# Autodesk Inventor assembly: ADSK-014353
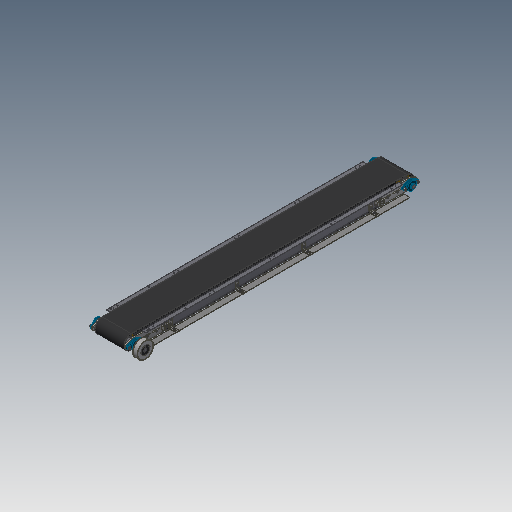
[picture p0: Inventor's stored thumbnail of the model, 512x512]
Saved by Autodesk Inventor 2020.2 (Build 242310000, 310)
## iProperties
Created: 2019-10
Part Number: ADSK-014353
Document SubType Name: Assembly
Designer: lutzd
Mass: 90371.3 g
Surface Area: 57832.2 cm^2
Volume: 15767.9 cm^3
Density: 5.73136 g/cm^3
VLDS_Profile: Default Assembly
VLDS_TimeStamp: 2016-07-29
VLDS_FailCnt: 0
VLDS_AcceptCnt: 0
Dimensions: 2353,4x1828,9x416 mm
Mass: 90,371 kg
DocNumber: ADSK-014353
Folder: 01 - Themengebiete\Simplification\01 - Packaging machine\
VDS_Category: 3D Komponenten
VDS_NumSchm: Autodesk
Title: belt conveyor
Author: lutzd
Revision Number: -
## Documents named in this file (23)
- D:\07 - DEMODATEN\OTX 2019 - Dataset - UPDATE - Dez2019\Designs\07-Packing machine\ADSK-014353.iam
- D:\07 - DEMODATEN\OTX 2019 - Dataset - UPDATE - Dez2019\Designs\07-Packing machine\500533.iam
- D:\07 - DEMODATEN\OTX 2019 - Dataset - UPDATE - Dez2019\Designs\07-Packing machine\Parts\ADSK-011789.ipt
- D:\07 - DEMODATEN\OTX 2019 - Dataset - UPDATE - Dez2019\Designs\07-Packing machine\Parts\ADSK-011476.ipt
- D:\07 - DEMODATEN\OTX 2019 - Dataset - UPDATE - Dez2019\Designs\07-Packing machine\Parts\ADSK-011712.ipt
- D:\07 - DEMODATEN\OTX 2019 - Dataset - UPDATE - Dez2019\Designs\07-Packing machine\Parts\ADSK-011477.ipt
- D:\07 - DEMODATEN\OTX 2019 - Dataset - UPDATE - Dez2019\Designs\07-Packing machine\Parts\ADSK-014338.ipt
- D:\07 - DEMODATEN\OTX 2019 - Dataset - UPDATE - Dez2019\Content Center Files\de-DE\DIN 125-1  B\DIN 125-1 - B 6,4.ipt
- D:\07 - DEMODATEN\OTX 2019 - Dataset - UPDATE - Dez2019\Content Center Files\de-DE\ISO 4032(1)\ISO 4032 - M6DIN EN.ipt
- D:\07 - DEMODATEN\OTX 2019 - Dataset - UPDATE - Dez2019\Content Center Files\de-DE\ISO 4762(2)\ISO 4762 - M6 x 20ISO.ipt
- D:\07 - DEMODATEN\OTX 2019 - Dataset - UPDATE - Dez2019\Content Center Files\de-DE\DIN 125-1  B\DIN 125-1 - B 8,4.ipt
- D:\07 - DEMODATEN\OTX 2019 - Dataset - UPDATE - Dez2019\Content Center Files\de-DE\ISO 4032(1)\ISO 4032 - M8DIN EN.ipt
- D:\07 - DEMODATEN\OTX 2019 - Dataset - UPDATE - Dez2019\Content Center Files\de-DE\ISO 4762(2)\ISO 4762 - M8 x 25ISO.ipt
- D:\07 - DEMODATEN\OTX 2019 - Dataset - UPDATE - Dez2019\Content Center Files\de-DE\ISO 4762(2)\ISO 4762 - M8 x 45ISO.ipt
- D:\07 - DEMODATEN\OTX 2019 - Dataset - UPDATE - Dez2019\Content Center Files\de-DE\DIN 125-1  B\DIN 125-1 - B 10,5.ipt
- D:\07 - DEMODATEN\OTX 2019 - Dataset - UPDATE - Dez2019\Content Center Files\de-DE\ISO 4762(2)\ISO 4762 - M10 x 25ISO.ipt
- D:\07 - DEMODATEN\OTX 2019 - Dataset - UPDATE - Dez2019\Content Center Files\de-DE\DIN 471(2)\DIN 471 - 52 x 2(1).ipt
- D:\07 - DEMODATEN\OTX 2019 - Dataset - UPDATE - Dez2019\Content Center Files\de-DE\ISO 2491 - A\ISO 2491 - A  6 x 4 x 36.ipt
- D:\07 - DEMODATEN\OTX 2019 - Dataset - UPDATE - Dez2019\Designs\07-Packing machine\ADSK-014342.iam
- D:\07 - DEMODATEN\OTX 2019 - Dataset - UPDATE - Dez2019\Designs\07-Packing machine\Parts\ADSK-014357.ipt
- D:\07 - DEMODATEN\OTX 2019 - Dataset - UPDATE - Dez2019\Designs\07-Packing machine\ADSK-014358.iam
- D:\07 - DEMODATEN\OTX 2019 - Dataset - UPDATE - Dez2019\Designs\07-Packing machine\Parts\ADSK-014367.ipt
- D:\07 - DEMODATEN\OTX 2019 - Dataset - UPDATE - Dez2019\Designs\07-Packing machine\Parts\ADSK-014506.ipt
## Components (188 placed, 22 different names)
1. ADSK-014358:1 [sub-assembly] — Passend:165, Passend:166, Passend:167, Passend:168, Fluchtend:10, Fluchtend:11, Fluchtend:12, Fluchtend:13, Passend:169, Passend:170, Passend:171, Passend:172, Passend:173, Passend:174, Passend:177, Passend:178, Passend:181, Passend:182, Passend:185, Passend:186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
2. 500533:1 [sub-assembly]
3. ADSK-011789:1
4. ADSK-011476:1
5. ADSK-011712:1
6. 500533:2 [sub-assembly]
7. ADSK-011712:2
8. 500533:3 [sub-assembly]
9. 500533:4 [sub-assembly]
10. ADSK-011477:1
11. ADSK-011712:3
12. ADSK-011712:4
13. ADSK-011789:2
14. ADSK-011789:3
15. ADSK-011789:4
16. ADSK-014357:1
17. ADSK-014338:1 — Passend:195, Passend:197, Passend:199, Passend:224, Passend:226, Passend:228, Passend:230
18. ADSK-014338:2
19. ADSK-014338:3
20. ADSK-014338:4 — Passend:201, Passend:203, Passend:205, Passend:207
21. ADSK-014342:1 [sub-assembly]
22. ADSK-014338:5 — Passend:165, Fluchtend:13, Passend:169, Passend:187, Passend:188
23. ADSK-014338:6 — Passend:166, Fluchtend:12, Passend:170, Passend:183, Passend:184, Passend:189, Fluchtend:15
24. ADSK-014338:7 — Passend:167, Fluchtend:11, Passend:171, Passend:175, Passend:176
25. ADSK-014338:8 — Passend:168, Fluchtend:10, Passend:172, Passend:179, Passend:180, Passend:191, Fluchtend:16
26. ADSK-014506:1 — Fluchtend:14, Passend:189, Fluchtend:15
27. ADSK-014367:2 — Passend:190, Passend:191, Fluchtend:16
28. DIN 125-1 B B 6,4:49
29. DIN 125-1 B B 6,4:50 — Passend:226
30. DIN 125-1 B B 6,4:51 — Passend:228
31. DIN 125-1 B B 6,4:52 — Passend:230
32. DIN 125-1 B B 6,4:53
33. DIN 125-1 B B 6,4:54
34. DIN EN 24032 M6:24
35. DIN EN 24032 M6:25
36. ISO 4762 M6 x 20:25
37. ISO 4762 M6 x 20:26
38. DIN EN 24032 M6:26
39. ISO 4762 M6 x 20:27
40. DIN 125-1 B B 6,4:34
41. DIN 125-1 B B 6,4:35
42. DIN 125-1 B B 6,4:36
43. DIN 125-1 B B 6,4:38 — Passend:195
44. DIN 125-1 B B 6,4:39 — Passend:197
45. DIN 125-1 B B 6,4:40 — Passend:199
46. DIN 125-1 B B 6,4:41 — Passend:217, Passend:219, Passend:221, Passend:223
47. DIN 125-1 B B 6,4:42
48. DIN 125-1 B B 6,4:43
49. DIN 125-1 B B 6,4:44
50. DIN 125-1 B B 6,4:45 — Passend:201
51. DIN 125-1 B B 6,4:46 — Passend:203
52. DIN 125-1 B B 6,4:47 — Passend:205
53. DIN 125-1 B B 6,4:48 — Passend:207
54. DIN EN 24032 M6:17
55. DIN EN 24032 M6:18
56. DIN EN 24032 M6:19
57. DIN EN 24032 M6:20
58. DIN EN 24032 M6:21
59. DIN EN 24032 M6:22
60. DIN EN 24032 M6:23
61. ISO 4762 M6 x 20:18
62. ISO 4762 M6 x 20:19
63. ISO 4762 M6 x 20:20
64. ISO 4762 M6 x 20:21 — Passend:217
65. ISO 4762 M6 x 20:22 — Passend:219
66. ISO 4762 M6 x 20:23 — Passend:221
67. ISO 4762 M6 x 20:24 — Passend:223
68. DIN 125-1 B B 6,4:17 — Einfügen:42, Passend:175
69. ISO 4762 M6 x 20:9 — Einfügen:42, Passend:173
70. DIN 125-1 B B 6,4:18 — Passend:176
71. ISO 4762 M6 x 20:10 — Passend:174
72. DIN 125-1 B B 6,4:19 — Passend:179
73. ISO 4762 M6 x 20:11 — Passend:177
74. DIN 125-1 B B 6,4:20 — Passend:180
75. ISO 4762 M6 x 20:12 — Passend:178
76. DIN 125-1 B B 6,4:21 — Passend:183
77. ISO 4762 M6 x 20:13 — Passend:181
78. DIN 125-1 B B 6,4:22 — Passend:184
79. ISO 4762 M6 x 20:14 — Passend:182
80. DIN 125-1 B B 6,4:23 — Passend:188
81. ISO 4762 M6 x 20:15 — Passend:185
82. DIN 125-1 B B 6,4:24 — Passend:187
83. ISO 4762 M6 x 20:16 — Passend:186
84. DIN 125-1 B B 6,4:25 — Einfügen:56
85. DIN EN 24032 M6:9
86. DIN 125-1 B B 6,4:26 — Einfügen:57
87. DIN EN 24032 M6:10
88. DIN 125-1 B B 6,4:27 — Einfügen:55
89. DIN EN 24032 M6:11
90. DIN 125-1 B B 6,4:28 — Einfügen:54
91. DIN EN 24032 M6:12
92. DIN 125-1 B B 6,4:29 — Einfügen:62
93. DIN EN 24032 M6:13
94. DIN 125-1 B B 6,4:30 — Einfügen:63
95. DIN EN 24032 M6:14
96. DIN 125-1 B B 6,4:31 — Einfügen:64
97. DIN EN 24032 M6:15
98. DIN 125-1 B B 6,4:32 — Einfügen:65
99. DIN EN 24032 M6:16
100. DIN 125-1 B B 6,4:2
101. DIN 125-1 B B 6,4:4
102. DIN 125-1 B B 6,4:6
103. DIN 125-1 B B 6,4:8
104. DIN 125-1 B B 6,4:9
105. DIN 125-1 B B 6,4:10
106. DIN 125-1 B B 6,4:11
107. DIN 125-1 B B 6,4:12
108. DIN 125-1 B B 6,4:13
109. DIN 125-1 B B 6,4:14
110. DIN 125-1 B B 6,4:15
111. DIN 125-1 B B 6,4:16
112. DIN EN 24032 M6:1
113. DIN EN 24032 M6:2
114. DIN EN 24032 M6:3
115. DIN EN 24032 M6:4
116. DIN EN 24032 M6:7
117. DIN EN 24032 M6:8
118. ISO 4762 M6 x 20:1
119. ISO 4762 M6 x 20:4
120. ISO 4762 M6 x 20:5
121. ISO 4762 M6 x 20:6
122. ISO 4762 M6 x 20:7
123. ISO 4762 M6 x 20:8
124. DIN 125-1 B B 8,4:1
125. DIN 125-1 B B 8,4:2
126. DIN 125-1 B B 8,4:3
127. DIN 125-1 B B 8,4:4
128. DIN 125-1 B B 8,4:5
129. DIN 125-1 B B 8,4:6
130. DIN 125-1 B B 8,4:7
131. DIN 125-1 B B 8,4:8
132. DIN 125-1 B B 8,4:9
133. DIN 125-1 B B 8,4:10
134. DIN 125-1 B B 8,4:11
135. DIN 125-1 B B 8,4:12
136. DIN 125-1 B B 8,4:13
137. DIN 125-1 B B 8,4:14
138. DIN 125-1 B B 8,4:15
139. DIN 125-1 B B 8,4:16
140. DIN EN 24032 M8:1
141. DIN EN 24032 M8:2
142. DIN EN 24032 M8:3
143. DIN EN 24032 M8:4
144. DIN EN 24032 M8:5
145. DIN EN 24032 M8:6
146. DIN EN 24032 M8:7
147. DIN EN 24032 M8:8
148. ISO 4762 M8 x 25:1
149. ISO 4762 M8 x 25:2
150. ISO 4762 M8 x 25:3
151. ISO 4762 M8 x 25:4
152. ISO 4762 M8 x 25:5
153. ISO 4762 M8 x 25:6
154. ISO 4762 M8 x 25:7
155. ISO 4762 M8 x 25:8
156. ISO 4762 M8 x 45:1
157. ISO 4762 M8 x 45:2
158. ISO 4762 M8 x 45:3
159. ISO 4762 M8 x 45:4
160. DIN EN 24032 M8:9
161. DIN EN 24032 M8:10
162. DIN EN 24032 M8:11
163. DIN EN 24032 M8:12
164. DIN 125-1 B B 10,5:1
165. DIN 125-1 B B 10,5:2
166. DIN 125-1 B B 10,5:3
167. DIN 125-1 B B 10,5:4
168. DIN 125-1 B B 10,5:5
169. DIN 125-1 B B 10,5:6
170. DIN 125-1 B B 10,5:7
171. DIN 125-1 B B 10,5:8
172. ISO 4762 M10 x 25:1
173. ISO 4762 M10 x 25:2
174. ISO 4762 M10 x 25:3
175. ISO 4762 M10 x 25:4
176. ISO 4762 M10 x 25:5
177. ISO 4762 M10 x 25:6
178. ISO 4762 M10 x 25:7
179. ISO 4762 M10 x 25:8
180. DIN 471 > 9mm <= 300mm 52 x 2:1
181. DIN 471 > 9mm <= 300mm 52 x 2:2
182. DIN 471 > 9mm <= 300mm 52 x 2:3
183. DIN 471 > 9mm <= 300mm 52 x 2:4
184. DIN 471 > 9mm <= 300mm 52 x 2:5
185. DIN 471 > 9mm <= 300mm 52 x 2:6
186. DIN 471 > 9mm <= 300mm 52 x 2:7
187. DIN 471 > 9mm <= 300mm 52 x 2:8
188. ISO 2491 A A  6 x 4 x 36:1
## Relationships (58: Mate 42, Insert 9, Flush 7)
- Passend:165 [Mate]: ADSK-014358:1 ↔ ADSK-014338:5
- Passend:166 [Mate]: ADSK-014358:1 ↔ ADSK-014338:6
- Passend:167 [Mate]: ADSK-014358:1 ↔ ADSK-014338:7
- Passend:168 [Mate]: ADSK-014358:1 ↔ ADSK-014338:8
- Fluchtend:10 [Flush]: ADSK-014358:1 ↔ ADSK-014338:8
- Fluchtend:11 [Flush]: ADSK-014358:1 ↔ ADSK-014338:7
- Fluchtend:12 [Flush]: ADSK-014358:1 ↔ ADSK-014338:6
- Fluchtend:13 [Flush]: ADSK-014358:1 ↔ ADSK-014338:5
- Passend:169 [Mate]: ADSK-014358:1 ↔ ADSK-014338:5
- Passend:170 [Mate]: ADSK-014358:1 ↔ ADSK-014338:6
- Passend:171 [Mate]: ADSK-014358:1 ↔ ADSK-014338:7
- Passend:172 [Mate]: ADSK-014358:1 ↔ ADSK-014338:8
- Einfügen:42 [Insert]: DIN 125-1 B B 6,4:17 ↔ ISO 4762 M6 x 20:9
- Passend:173 [Mate]: ADSK-014358:1 ↔ ISO 4762 M6 x 20:9
- Passend:174 [Mate]: ADSK-014358:1 ↔ ISO 4762 M6 x 20:10
- Passend:175 [Mate]: ADSK-014338:7 ↔ DIN 125-1 B B 6,4:17
- Passend:176 [Mate]: ADSK-014338:7 ↔ DIN 125-1 B B 6,4:18
- Passend:177 [Mate]: ADSK-014358:1 ↔ ISO 4762 M6 x 20:11
- Passend:178 [Mate]: ADSK-014358:1 ↔ ISO 4762 M6 x 20:12
- Passend:179 [Mate]: ADSK-014338:8 ↔ DIN 125-1 B B 6,4:19
- Passend:180 [Mate]: ADSK-014338:8 ↔ DIN 125-1 B B 6,4:20
- Passend:181 [Mate]: ADSK-014358:1 ↔ ISO 4762 M6 x 20:13
- Passend:182 [Mate]: ADSK-014358:1 ↔ ISO 4762 M6 x 20:14
- Passend:183 [Mate]: ADSK-014338:6 ↔ DIN 125-1 B B 6,4:21
- Passend:184 [Mate]: ADSK-014338:6 ↔ DIN 125-1 B B 6,4:22
- Passend:185 [Mate]: ADSK-014358:1 ↔ ISO 4762 M6 x 20:15
- Passend:186 [Mate]: ADSK-014358:1 ↔ ISO 4762 M6 x 20:16
- Passend:187 [Mate]: ADSK-014338:5 ↔ DIN 125-1 B B 6,4:24
- Passend:188 [Mate]: ADSK-014338:5 ↔ DIN 125-1 B B 6,4:23
- Einfügen:54 [Insert]: ADSK-014358:1 ↔ DIN 125-1 B B 6,4:28
- Einfügen:55 [Insert]: ADSK-014358:1 ↔ DIN 125-1 B B 6,4:27
- Einfügen:56 [Insert]: ADSK-014358:1 ↔ DIN 125-1 B B 6,4:25
- Einfügen:57 [Insert]: ADSK-014358:1 ↔ DIN 125-1 B B 6,4:26
- Einfügen:62 [Insert]: ADSK-014358:1 ↔ DIN 125-1 B B 6,4:29
- Einfügen:63 [Insert]: ADSK-014358:1 ↔ DIN 125-1 B B 6,4:30
- Einfügen:64 [Insert]: ADSK-014358:1 ↔ DIN 125-1 B B 6,4:31
- Einfügen:65 [Insert]: ADSK-014358:1 ↔ DIN 125-1 B B 6,4:32
- Fluchtend:14 [Flush]: ADSK-014506:1
- Passend:189 [Mate]: ADSK-014338:6 ↔ ADSK-014506:1
- Fluchtend:15 [Flush]: ADSK-014338:6 ↔ ADSK-014506:1
- Passend:190 [Mate]: ADSK-014367:2
- Passend:191 [Mate]: ADSK-014338:8 ↔ ADSK-014367:2
- Fluchtend:16 [Flush]: ADSK-014338:8 ↔ ADSK-014367:2
- Passend:195 [Mate]: ADSK-014338:1 ↔ DIN 125-1 B B 6,4:38
- Passend:197 [Mate]: ADSK-014338:1 ↔ DIN 125-1 B B 6,4:39
- Passend:199 [Mate]: ADSK-014338:1 ↔ DIN 125-1 B B 6,4:40
- Passend:201 [Mate]: ADSK-014338:4 ↔ DIN 125-1 B B 6,4:45
- Passend:203 [Mate]: ADSK-014338:4 ↔ DIN 125-1 B B 6,4:46
- Passend:205 [Mate]: ADSK-014338:4 ↔ DIN 125-1 B B 6,4:47
- Passend:207 [Mate]: ADSK-014338:4 ↔ DIN 125-1 B B 6,4:48
- Passend:217 [Mate]: DIN 125-1 B B 6,4:41 ↔ ISO 4762 M6 x 20:21
- Passend:219 [Mate]: DIN 125-1 B B 6,4:41 ↔ ISO 4762 M6 x 20:22
- Passend:221 [Mate]: DIN 125-1 B B 6,4:41 ↔ ISO 4762 M6 x 20:23
- Passend:223 [Mate]: DIN 125-1 B B 6,4:41 ↔ ISO 4762 M6 x 20:24
- Passend:224 [Mate]: ADSK-014358:1 ↔ ADSK-014338:1
- Passend:226 [Mate]: ADSK-014338:1 ↔ DIN 125-1 B B 6,4:50
- Passend:228 [Mate]: ADSK-014338:1 ↔ DIN 125-1 B B 6,4:51
- Passend:230 [Mate]: ADSK-014338:1 ↔ DIN 125-1 B B 6,4:52
## Named parameters: d227_d226 = 0, d232_d226 = 0, d233_d226 = 0, d238_d226 = 0, d239_d226 = 0, d244_d226 = 0, d245_d226 = 0, d250_d639 = 0, d251_d639 = 0, d252_d639 = 0, d253_d639 = 0, d258_d639 = 0, d259_d639 = 0, d260_d639 = 0, d261_d639 = 0
